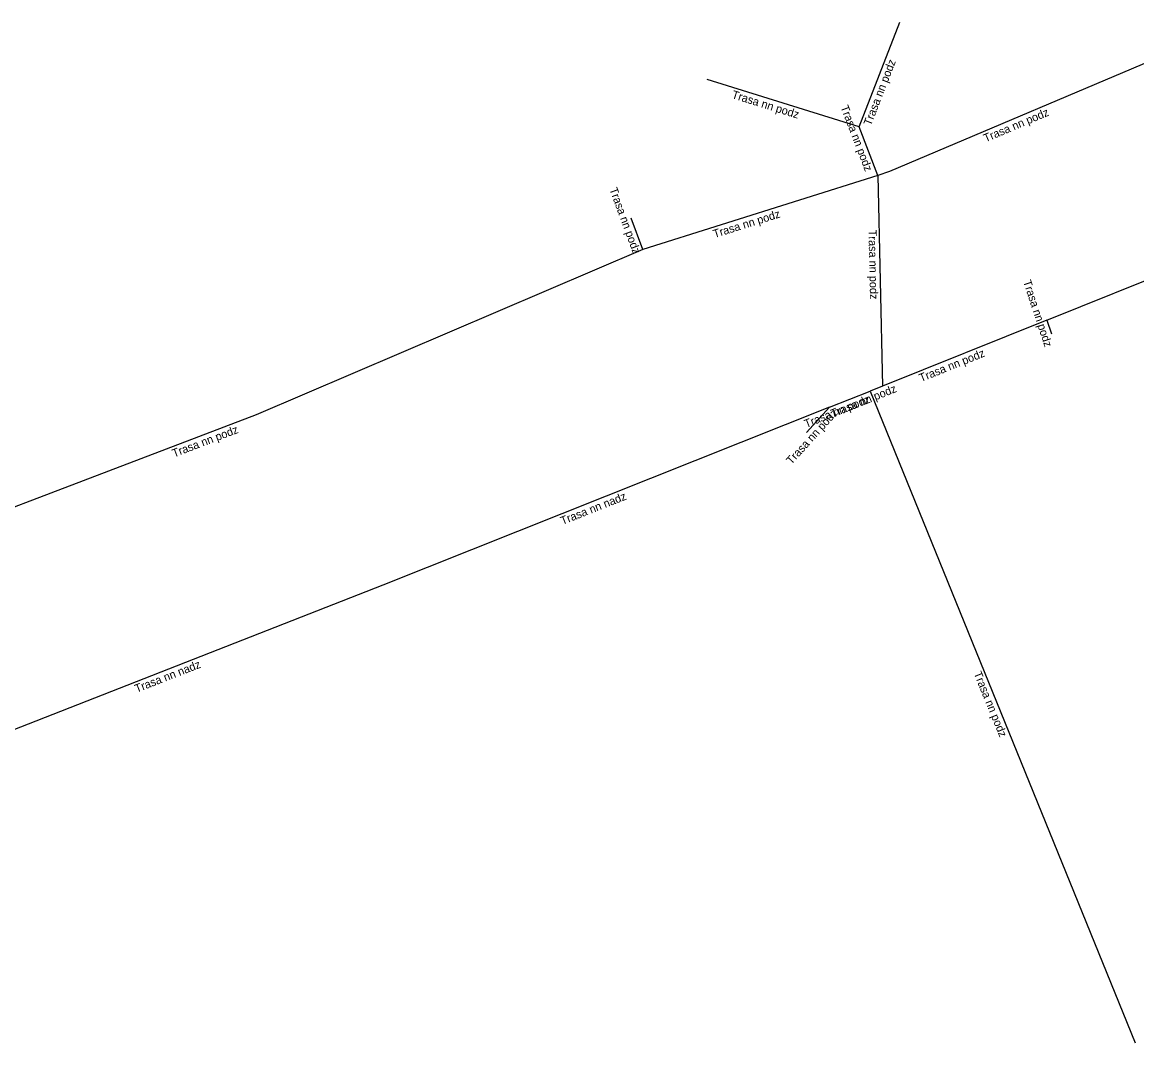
# Model space of a CAD drawing. Extents: x -711262 to -710488, y -1025222 to -1024810.
# Drawn here: x -710701.4 to -710633.1, y -1024931.5 to -1024868.9 of the extents above; entities that cross this region are included whole.
import ezdxf

# ---------------------------------------------------------------- set-up
doc = ezdxf.new("R2010")
doc.units = 0
doc.layers.add('Popiskový text - Ostatní atributy Trasy', color=7, linetype='Continuous')
doc.layers.add('Spojnice NN', color=7, linetype='Continuous')

msp = doc.modelspace()

# ---------------------------------------------------------------- linework, layer by layer
at = {"layer": 'Spojnice NN'}
for points in [[(-710650.08, -1024875.31), (-710647.6, -1024868.9)], [(-710630.46, -1024870.53), (-710648.23, -1024878.05), (-710648.94, -1024878.3)], [(-710650.08, -1024875.31), (-710659.4, -1024872.4)], [(-710648.94, -1024878.3), (-710650.08, -1024875.31)], [(-710638.579, -1024887.153), (-710630.35, -1024883.85), (-710613.08, -1024876.93)], [(-710648.94, -1024878.3), (-710663.36, -1024882.83)], [(-710648.94, -1024878.3), (-710648.657, -1024891.207)], [(-710663.36, -1024882.83), (-710664.07, -1024880.9)], [(-710663.36, -1024882.83), (-710687.06, -1024892.96), (-710715.81, -1024903.92)], [(-710638.579, -1024887.153), (-710648.657, -1024891.207)], [(-710638.579, -1024887.153), (-710638.3, -1024888)], [(-710651.9, -1024892.5), (-710649.41, -1024891.51)], [(-710648.657, -1024891.207), (-710649.41, -1024891.51)], [(-710649.41, -1024891.51), (-710633.16, -1024931.45)], [(-710651.9, -1024892.5), (-710679.3, -1024903.4)], [(-710651.9, -1024892.5), (-710653.31, -1024894.05)], [(-710679.3, -1024903.4), (-710704.1, -1024913.1)]]:
    msp.add_lwpolyline(points, dxfattribs=at)

# ---------------------------------------------------------------- texts
at = {"layer": 'Popiskový text - Ostatní atributy Trasy'}
for s, rotation, p in [('Trasa nn podz', 68.84877, (-710649.37, -1024875.275)), ('Trasa nn podz', 342.65998, (-710657.938, -1024873.538)), ('Trasa nn podz', 290.87039, (-710651.239, -1024874.096)), ('Trasa nn podz', 22.93736, (-710642.337, -1024876.262)), ('Trasa nn podz', 290.19734, (-710665.411, -1024879.135)), ('Trasa nn podz', 17.43996, (-710658.958, -1024882.129)), ('Trasa nn podz', 271.25607, (-710649.517, -1024881.621)), ('Trasa nn podz', 288.23177, (-710640.041, -1024884.791)), ('Trasa nn podz', 21.91307, (-710646.296, -1024890.958)), ('Trasa nn podz', 21.91938, (-710651.711, -1024893.137)), ('Trasa nn podz', 21.68229, (-710653.34, -1024893.772)), ('Trasa nn podz', 47.70792, (-710654.242, -1024896.041)), ('Trasa nn podz', 20.86772, (-710692.103, -1024895.578)), ('Trasa nn nadz', 21.69317, (-710668.284, -1024899.718)), ('Trasa nn nadz', 21.36191, (-710694.394, -1024910.002)), ('Trasa nn podz', 292.13946, (-710643.074, -1024908.81))]:
    msp.add_text(s, height=0.5, rotation=rotation, dxfattribs=at).set_placement(p)

doc.saveas('drawing.dxf')
